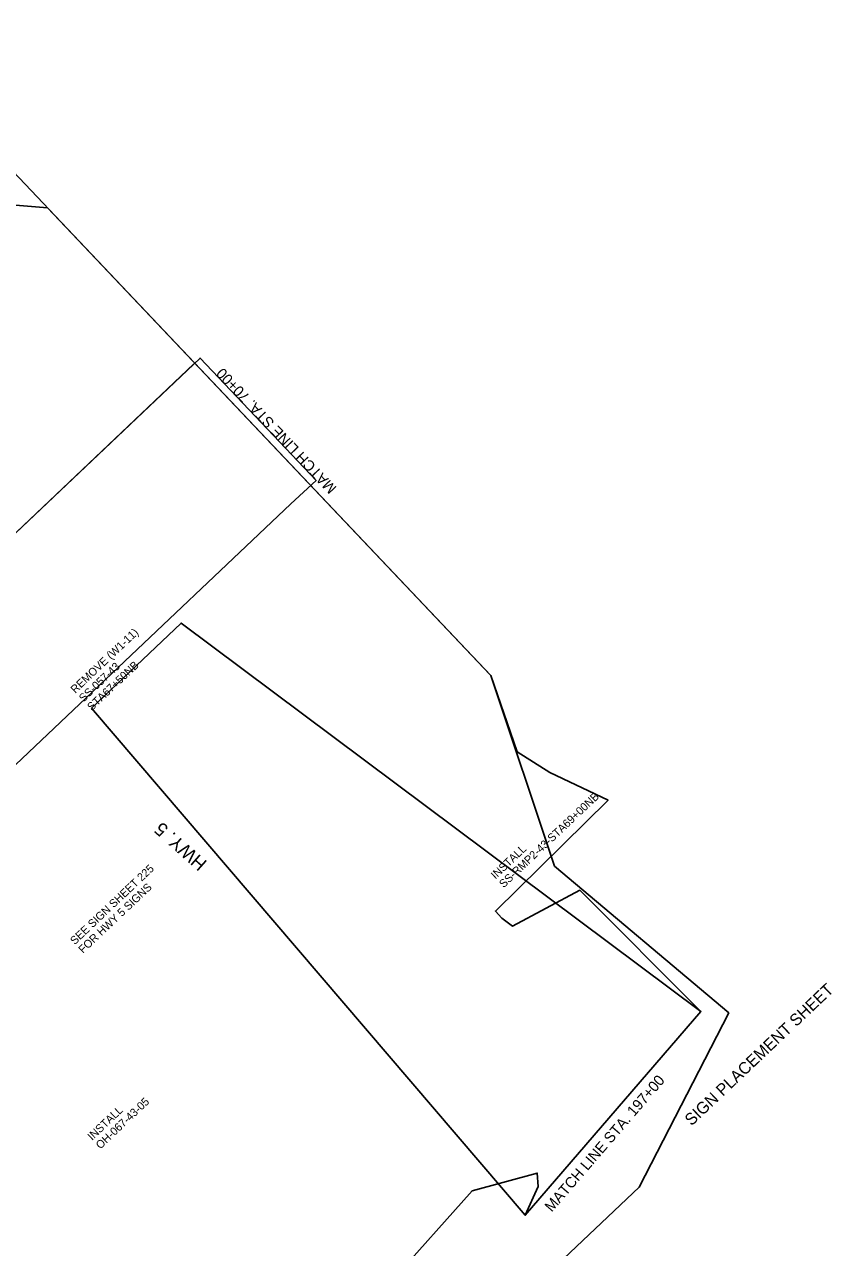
# Model space of a CAD drawing. Extents: x 1289840 to 1295361, y 220865 to 226414.
# Drawn here: x 1293102 to 1293707, y 223498 to 224415 of the extents above; entities that cross this region are included whole.
import ezdxf

# ---------------------------------------------------------------- set-up
doc = ezdxf.new("R2010")
doc.units = 0
for name, color, linetype in [('5', 7, 'Continuous'), ('60', 7, 'Continuous'), ('Plan Notes', 7, 'Continuous'), ('R_Annotation', 7, 'Continuous'), ('R_No Plot', 7, 'Continuous'), ('R_Proposed Road', 7, 'Continuous')]:
    doc.layers.add(name, color=color, linetype=linetype)

msp = doc.modelspace()

# ---------------------------------------------------------------- linework, layer by layer
msp.add_lwpolyline([(1292980.68, 223090.12), (1292443.5, 222809.76), (1291900.12, 223383.09), (1292988.84, 224414.93), (1293451.49, 223926.78), (1293499.16, 223783.99), (1293629.78, 223673.86), (1293562.47, 223543.22), (1293152.68, 223154.83)], close=True)
msp.add_lwpolyline([(1292371.23, 223352.91), (1292711.02, 223669.57), (1292746.9, 223703.57), (1293233.52, 224164.77), (1293320.5, 224073), (1293301.58, 224055.67), (1293004.15, 223773.78), (1292841.84, 223619.95), (1292807.03, 223597.98), (1292782.66, 223574.88), (1292405.59, 223217.51)])
at = {"layer": '5'}
for p, q in [((1293450.66, 223927.65), (1293119.13, 224277.46)), ((1293477.25, 223522.23), (1293608.84, 223674.88))]:
    msp.add_line(p, q, dxfattribs=at)
at = {"layer": 'R_No Plot'}
msp.add_lwpolyline([(1293377.29, 223473.16), (1293437.48, 223540.62), (1293486.19, 223553.77), (1293486.83, 223543.72), (1293477.25, 223522.23), (1293608.84, 223674.88), (1293518.1, 223765.88), (1293467.76, 223739.01), (1293459.71, 223744.94), (1293454.82, 223750.21), (1293539.24, 223833.35), (1293495.69, 223854.16), (1293471.07, 223869.54), (1293451.49, 223926.78), (1293119.13, 224277.46), (1293022.5, 224285.34)], dxfattribs=at)
msp.add_lwpolyline([(1293152.09, 223902.41), (1293219.36, 223966.12), (1293608.84, 223674.88), (1293477.25, 223522.23)], close=True, dxfattribs=at)
at = {"layer": 'R_Proposed Road'}
msp.add_line((1292348.11, 223325.62), (1293228.94, 224160.43), dxfattribs=at)

# ---------------------------------------------------------------- texts
at = {"layer": '60'}
msp.add_text('SIGN PLACEMENT SHEET', height=8.8703, rotation=43.46361, dxfattribs=at).set_placement((1293601.82, 223588.76))
at = {"layer": 'Plan Notes'}
for s, height, rotation, p in [('MATCH LINE STA. 70+00', 8, 133.46361, (1293336.38, 224067.72)), ('HWY. 5', 10, 138.46361, (1293239.41, 223787.06)), ('MATCH LINE STA. 197+00', 8, 49.23922, (1293497.09, 223524.15))]:
    msp.add_text(s, height=height, rotation=rotation, dxfattribs=at).set_placement(p)
at = {"layer": 'R_Annotation'}
for s, p in [('REMOVE (W1-11)', (1293140, 223913.09)), ('SS-057-43', (1293146.19, 223906.56)), ('STA67+50NB', (1293152.38, 223900.02)), ('SS-RMP2-43-STA69+00NB', (1293461.07, 223767.27)), ('INSTALL', (1293454.88, 223773.81)), ('SEE SIGN SHEET 225', (1293139.62, 223724.66)), ('FOR HWY 5 SIGNS', (1293145.81, 223718.12)), ('OH-067-43-05', (1293158.8, 223571.41)), ('INSTALL', (1293152.61, 223577.95))]:
    msp.add_text(s, height=6, rotation=43.43866, dxfattribs=at).set_placement(p)

doc.saveas('drawing.dxf')
